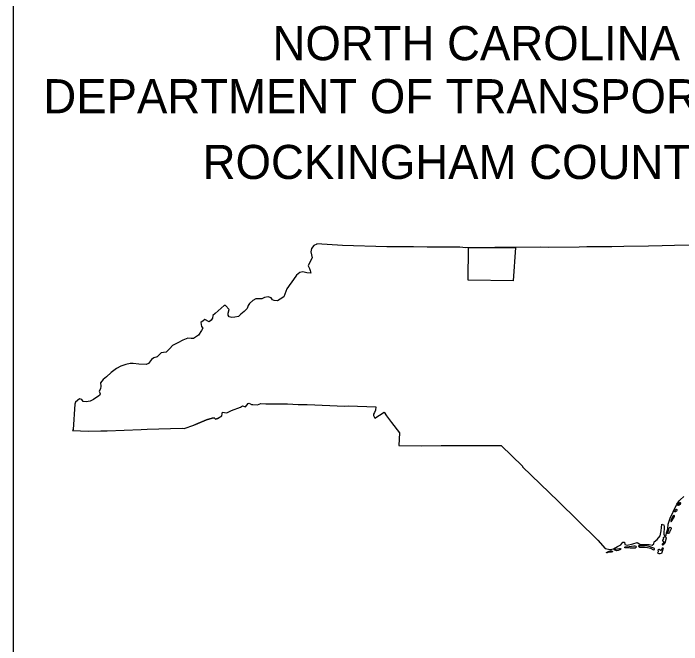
# Model space of a CAD drawing. Extents: x 1184121 to 1184360, y 1246506 to 1246661.
# Drawn here: x 1184344.34 to 1184354.28, y 1246642.37 to 1246651.76 of the extents above; entities that cross this region are included whole.
import ezdxf

# ---------------------------------------------------------------- set-up
doc = ezdxf.new("R2010")
doc.units = 0
for name, color, linetype in [('Old_Level_20', 7, 'Continuous'), ('P_RDY_Dimension_Text', 7, 'Continuous'), ('Sheet Plan CELL', 7, 'Continuous')]:
    doc.layers.add(name, color=color, linetype=linetype)

msp = doc.modelspace()

# ---------------------------------------------------------------- linework, layer by layer
at = {"layer": 'Old_Level_20'}
for points in [[(1184354.7611, 1246648.3177), (1184354.1767, 1246648.3048), (1184353.9956, 1246648.2989), (1184353.793, 1246648.2944), (1184353.4225, 1246648.2904), (1184353.2482, 1246648.2882), (1184352.8726, 1246648.2875), (1184352.7608, 1246648.2803), (1184352.3102, 1246648.2784), (1184352.1865, 1246648.2823), (1184351.8141, 1246648.2741), (1184351.5071, 1246648.2784), (1184351.0744, 1246648.2734), (1184350.9865, 1246648.2787), (1184350.4979, 1246648.28), (1184350.2955, 1246648.2838), (1184349.971, 1246648.287), (1184349.8998, 1246648.2853), (1184349.2409, 1246648.3037), (1184348.8606, 1246648.329), (1184348.8559, 1246648.3238), (1184348.8144, 1246648.308), (1184348.7804, 1246648.2601), (1184348.7682, 1246648.2133), (1184348.7797, 1246648.1674), (1184348.7873, 1246648.1219), (1184348.7549, 1246648.0565), (1184348.7285, 1246648.0059), (1184348.7482, 1246647.9627), (1184348.7598, 1246647.9322), (1184348.7684, 1246647.8944), (1184348.7101, 1246647.8982), (1184348.6514, 1246647.9135), (1184348.605, 1246647.9041), (1184348.5568, 1246647.8659), (1184348.4768, 1246647.7508), (1184348.47, 1246647.744), (1184348.4123, 1246647.6627), (1184348.367, 1246647.5414), (1184348.314, 1246647.5097), (1184348.2713, 1246647.4824), (1184348.2249, 1246647.4864), (1184348.1973, 1246647.4995), (1184348.1774, 1246647.527), (1184348.1345, 1246647.542), (1184348.0806, 1246647.5334), (1184348.0392, 1246647.5155), (1184348.0036, 1246647.5122), (1184347.9507, 1246647.5111), (1184347.9069, 1246647.4896), (1184347.8559, 1246647.4421), (1184347.8345, 1246647.4121), (1184347.8196, 1246647.3716), (1184347.7764, 1246647.3232), (1184347.7286, 1246647.2849), (1184347.6914, 1246647.2529), (1184347.6389, 1246647.2382), (1184347.5936, 1246647.2342), (1184347.5561, 1246647.2464), (1184347.5374, 1246647.2679), (1184347.5375, 1246647.3005), (1184347.5542, 1246647.3561), (1184347.5008, 1246647.4125), (1184347.4816, 1246647.4148), (1184347.344, 1246647.2969), (1184347.3127, 1246647.2642), (1184347.3081, 1246647.2263), (1184347.2885, 1246647.1941), (1184347.2545, 1246647.1713), (1184347.1904, 1246647.2039), (1184347.1667, 1246647.1856), (1184347.1325, 1246647.1609), (1184347.1412, 1246647.1042), (1184347.1634, 1246647.0786), (1184347.1416, 1246647.0429), (1184347.0981, 1246646.9733), (1184347.0704, 1246646.9536)], [(1184347.0704, 1246646.9536), (1184347.0222, 1246646.9248), (1184346.9892, 1246646.9248), (1184346.9413, 1246646.9304), (1184346.8675, 1246646.8988), (1184346.7932, 1246646.8615), (1184346.7122, 1246646.8173), (1184346.6702, 1246646.7743), (1184346.6433, 1246646.743), (1184346.6191, 1246646.719), (1184346.5759, 1246646.7144), (1184346.5406, 1246646.7107), (1184346.5119, 1246646.6815), (1184346.4812, 1246646.6506), (1184346.4348, 1246646.6349), (1184346.4009, 1246646.61), (1184346.3534, 1246646.5505), (1184346.3187, 1246646.5353), (1184346.2112, 1246646.5435), (1184346.127, 1246646.5528), (1184346.0826, 1246646.5538), (1184346.0169, 1246646.5382), (1184345.9441, 1246646.5099), (1184345.8766, 1246646.4772), (1184345.7983, 1246646.4171), (1184345.7277, 1246646.3561), (1184345.6786, 1246646.3137), (1184345.6425, 1246646.2662), (1184345.6446, 1246646.2146), (1184345.6402, 1246646.1751), (1184345.623, 1246646.1408), (1184345.6341, 1246646.1016), (1184345.6234, 1246646.0742), (1184345.5864, 1246646.0535), (1184345.5362, 1246646.017), (1184345.4851, 1246645.9901), (1184345.4263, 1246645.9811), (1184345.3829, 1246645.9894), (1184345.3626, 1246646.0163), (1184345.3291, 1246646.0273), (1184345.2699, 1246645.9784), (1184345.2587, 1246645.9454), (1184345.2321, 1246645.569), (1184345.2233, 1246645.5585), (1184345.4623, 1246645.5487), (1184345.6432, 1246645.5523), (1184345.7375, 1246645.5535), (1184346.243, 1246645.5721), (1184346.3358, 1246645.5769), (1184346.8547, 1246645.5917), (1184346.8865, 1246645.5842), (1184347.0309, 1246645.6338), (1184347.0514, 1246645.6446), (1184347.2177, 1246645.7142), (1184347.3018, 1246645.7402), (1184347.3312, 1246645.7443), (1184347.3521, 1246645.7266), (1184347.3784, 1246645.7368), (1184347.443, 1246645.7765), (1184347.4501, 1246645.8022), (1184347.455, 1246645.8263), (1184347.4835, 1246645.8229), (1184347.5179, 1246645.8206), (1184347.5911, 1246645.8517), (1184347.7212, 1246645.9042), (1184347.7525, 1246645.9232), (1184347.7948, 1246645.9066), (1184347.8361, 1246645.9586), (1184347.8542, 1246645.9639), (1184347.8846, 1246645.945), (1184347.9074, 1246645.9421), (1184347.9743, 1246645.9376), (1184348.0268, 1246645.9558), (1184348.1, 1246645.9543), (1184348.4221, 1246645.9515), (1184348.5814, 1246645.9443), (1184348.7144, 1246645.9423), (1184349.2751, 1246645.9176), (1184349.3317, 1246645.9214), (1184349.7378, 1246645.9098), (1184349.7287, 1246645.8596), (1184349.7177, 1246645.823), (1184349.6989, 1246645.799), (1184349.6997, 1246645.7779), (1184349.7234, 1246645.7404), (1184349.8576, 1246645.8284), (1184349.8961, 1246645.7735), (1184349.9708, 1246645.6756), (1184350.0856, 1246645.5225), (1184350.0795, 1246645.3334), (1184350.4098, 1246645.3282), (1184350.707, 1246645.3328), (1184351.2731, 1246645.3309), (1184351.576, 1246645.3326), (1184351.5989, 1246645.331), (1184351.9165, 1246645.0257), (1184351.9185, 1246645.014), (1184352.4489, 1246644.5042), (1184353.0399, 1246643.9248), (1184353.1471, 1246643.8016)], [(1184347.3784, 1246645.7368), (1184347.3521, 1246645.7266), (1184347.3312, 1246645.7443), (1184347.3018, 1246645.7402), (1184347.2177, 1246645.7142), (1184347.0514, 1246645.6446), (1184347.0309, 1246645.6338)], [(1184353.1471, 1246643.8016), (1184353.2207, 1246643.7857), (1184353.2709, 1246643.8), (1184353.3316, 1246643.8314), (1184353.3783, 1246643.8595), (1184353.4075, 1246643.8962), (1184353.4323, 1246643.8958), (1184353.4378, 1246643.8609), (1184353.4746, 1246643.8529), (1184353.5561, 1246643.8713), (1184353.6242, 1246643.8901), (1184353.6626, 1246643.8685), (1184353.734, 1246643.8621), (1184353.8006, 1246643.8603), (1184353.8467, 1246643.8506), (1184353.8715, 1246643.8728), (1184353.8763, 1246643.9003), (1184353.9224, 1246643.934), (1184353.9633, 1246643.9931), (1184353.9796, 1246644.0641), (1184353.9892, 1246644.1627), (1184353.9948, 1246644.1617), (1184354.0187, 1246644.1557), (1184354.0268, 1246644.126), (1184354.0171, 1246644.016), (1184354.023, 1246644.0016), (1184354.0355, 1246643.9928), (1184354.0479, 1246643.9929), (1184354.0535, 1246644.0009), (1184354.0606, 1246644.035), (1184354.079, 1246644.0962), (1184354.0833, 1246644.1636), (1184354.1125, 1246644.2532), (1184354.1598, 1246644.3474), (1184354.2142, 1246644.4593), (1184354.2482, 1246644.5103), (1184354.2605, 1246644.5253), (1184354.3157, 1246644.5764)], [(1184354.2307, 1246644.4502), (1184354.2411, 1246644.4676), (1184354.2521, 1246644.4795), (1184354.2588, 1246644.4844), (1184354.2637, 1246644.4848), (1184354.268, 1246644.4809), (1184354.2706, 1246644.4756), (1184354.265, 1246644.4694), (1184354.2556, 1246644.4568), (1184354.2473, 1246644.4484), (1184354.2348, 1246644.4416), (1184354.2311, 1246644.4416), (1184354.2286, 1246644.4433), (1184354.2275, 1246644.4455), (1184354.2307, 1246644.4502)], [(1184354.1793, 1246644.3518), (1184354.1851, 1246644.3645), (1184354.1924, 1246644.375), (1184354.1993, 1246644.3806), (1184354.2076, 1246644.385), (1184354.2124, 1246644.3836), (1184354.2142, 1246644.3794), (1184354.2111, 1246644.3694), (1184354.2058, 1246644.3575), (1184354.2, 1246644.3519), (1184354.1923, 1246644.3468), (1184354.1822, 1246644.3478), (1184354.1796, 1246644.349), (1184354.1791, 1246644.3527)], [(1184354.1237, 1246644.2186), (1184354.1224, 1246644.2063), (1184354.1246, 1246644.2053), (1184354.1295, 1246644.2061), (1184354.1366, 1246644.2101), (1184354.1408, 1246644.2154), (1184354.1769, 1246644.2762), (1184354.1782, 1246644.2842), (1184354.1767, 1246644.2885), (1184354.1714, 1246644.2921), (1184354.1662, 1246644.292), (1184354.1587, 1246644.2877), (1184354.1541, 1246644.2821), (1184354.1261, 1246644.2271), (1184354.1236, 1246644.2187)], [(1184354.0943, 1246644.0789), (1184354.0951, 1246644.0963), (1184354.0964, 1246644.1091), (1184354.1024, 1246644.1156), (1184354.1108, 1246644.1192), (1184354.119, 1246644.1168), (1184354.1272, 1246644.1106), (1184354.1271, 1246644.0946), (1184354.1054, 1246644.0432), (1184354.0932, 1246644.0285), (1184354.0822, 1246644.0231), (1184354.0754, 1246644.0262), (1184354.0746, 1246644.0347), (1184354.0833, 1246644.0532), (1184354.0946, 1246644.08)], [(1184354.019, 1246643.9479), (1184354.0119, 1246643.9363), (1184354.0003, 1246643.9281), (1184353.9986, 1246643.9245), (1184353.9993, 1246643.92), (1184354.0118, 1246643.9068), (1184354.0184, 1246643.9014), (1184354.0211, 1246643.8993), (1184354.021, 1246643.8922), (1184353.9959, 1246643.866), (1184353.9939, 1246643.8622), (1184354.0012, 1246643.8563), (1184354.0063, 1246643.8579), (1184354.0179, 1246643.8652), (1184354.037, 1246643.8878), (1184354.0577, 1246643.9589)], [(1184354.0577, 1246643.9589), (1184354.0473, 1246643.969), (1184354.0228, 1246643.9726), (1184354.0147, 1246643.9676), (1184354.0091, 1246643.9629), (1184354.0106, 1246643.9579), (1184354.019, 1246643.9479)], [(1184353.2992, 1246643.7936), (1184353.3598, 1246643.8014), (1184353.3719, 1246643.8012), (1184353.3776, 1246643.7992), (1184353.3756, 1246643.7899), (1184353.3671, 1246643.7831), (1184353.3414, 1246643.7728), (1184353.3215, 1246643.7701), (1184353.2902, 1246643.7779), (1184353.282, 1246643.782), (1184353.2872, 1246643.7888), (1184353.3007, 1246643.7947)], [(1184353.4466, 1246643.8268), (1184353.5058, 1246643.8314), (1184353.5713, 1246643.8425), (1184353.5876, 1246643.8434), (1184353.6012, 1246643.8362), (1184353.6087, 1246643.827), (1184353.607, 1246643.821), (1184353.5916, 1246643.8098), (1184353.5799, 1246643.8064), (1184353.5164, 1246643.8099), (1184353.4706, 1246643.8111), (1184353.4518, 1246643.8112), (1184353.4415, 1246643.8143), (1184353.4375, 1246643.8178), (1184353.4375, 1246643.8203), (1184353.4382, 1246643.8224), (1184353.4464, 1246643.826)], [(1184353.6411, 1246643.8366), (1184353.664, 1246643.8219), (1184353.6881, 1246643.823), (1184353.7335, 1246643.8214), (1184353.7747, 1246643.8169), (1184353.8209, 1246643.8069), (1184353.8552, 1246643.7889), (1184353.8695, 1246643.7827), (1184353.8822, 1246643.7885), (1184353.8792, 1246643.8005), (1184353.8692, 1246643.8075), (1184353.8001, 1246643.8307), (1184353.7446, 1246643.8414), (1184353.6538, 1246643.8424), (1184353.641, 1246643.8408), (1184353.6418, 1246643.8366)], [(1184353.9517, 1246643.794), (1184353.9745, 1246643.7779), (1184353.9803, 1246643.7759), (1184353.9886, 1246643.7859), (1184353.9996, 1246643.813), (1184354.006, 1246643.8159), (1184354.0111, 1246643.8075), (1184353.9898, 1246643.7455), (1184353.9851, 1246643.7305), (1184353.9667, 1246643.7218), (1184353.9511, 1246643.7209), (1184353.9369, 1246643.7264), (1184353.9324, 1246643.7405), (1184353.9379, 1246643.7576), (1184353.9362, 1246643.7817), (1184353.9383, 1246643.7867), (1184353.9502, 1246643.7947), (1184353.9538, 1246643.794)], [(1184353.167, 1246643.743), (1184353.1794, 1246643.7513), (1184353.2043, 1246643.7615), (1184353.2213, 1246643.7658), (1184353.2321, 1246643.7667), (1184353.2413, 1246643.7655), (1184353.2518, 1246643.7627), (1184353.2566, 1246643.7606), (1184353.2579, 1246643.7579), (1184353.257, 1246643.756), (1184353.245, 1246643.7494), (1184353.2422, 1246643.7505), (1184353.2397, 1246643.7525), (1184353.2285, 1246643.7503), (1184353.2057, 1246643.7459), (1184353.1863, 1246643.7407), (1184353.175, 1246643.7377), (1184353.1707, 1246643.7373), (1184353.1682, 1246643.74), (1184353.167, 1246643.743)]]:
    msp.add_lwpolyline(points, dxfattribs=at)
at = {"layer": 'P_RDY_Dimension_Text'}
msp.add_lwpolyline([(1184351.7806, 1246647.7817), (1184351.1083, 1246647.7899), (1184351.1134, 1246648.2734), (1184351.5232, 1246648.2782), (1184351.8141, 1246648.2741)], close=True, dxfattribs=at)
at = {"layer": 'Sheet Plan CELL'}
msp.add_line((1184344.3445, 1246508.8745), (1184344.348, 1246657.3636), dxfattribs=at)

# ---------------------------------------------------------------- texts
for s, p in [('NORTH CAROLINA', (1184348.1984, 1246651.0596)), ('DEPARTMENT OF TRANSPORTATION', (1184344.7898, 1246650.271)), ('ROCKINGHAM COUNTY', (1184347.1602, 1246649.294))]:
    msp.add_text(s, height=0.506702, rotation=0, dxfattribs=at).set_placement(p)

doc.saveas('drawing.dxf')
